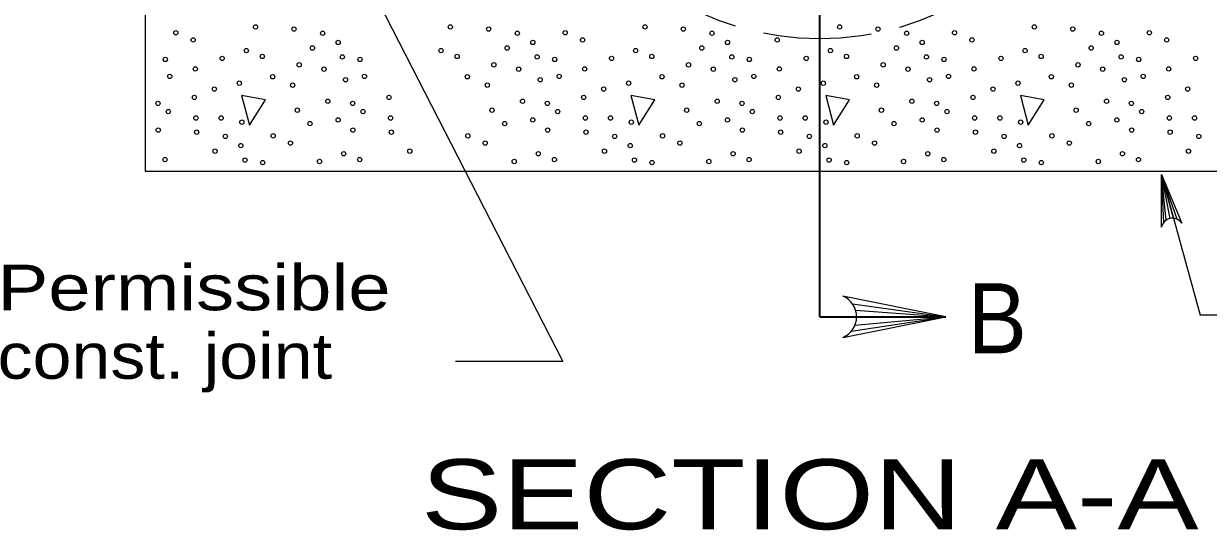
# Model space of a CAD drawing. Extents: x -410.5 to -376.5, y 1617.6 to 1661.6.
# Drawn here: x -405.776 to -401.715, y 1628.914 to 1630.65 of the extents above; entities that cross this region are included whole.
import ezdxf
from ezdxf.enums import TextEntityAlignment as Align

# ---------------------------------------------------------------- set-up
doc = ezdxf.new("R2010")
doc.units = 0
doc.header["$LTSCALE"] = 0.062
doc.linetypes.add('LONG_DASHED', pattern=[7.5, 6, -1.5])
doc.layers.add('1', color=7, linetype='Continuous', lineweight=13)

msp = doc.modelspace()

# ---------------------------------------------------------------- linework, layer by layer
at = {"layer": '1', "lineweight": 35}
for q in [(-403.04708, 1633.76367), (-402.61442, 1629.64583)]:
    msp.add_line((-403.04708, 1629.64583), q, dxfattribs=at)
at = {"layer": '1'}
for p, q in [((-401.84525, 1629.983), (-401.87542, 1630.13317)), ((-401.85883, 1629.97742), (-401.87542, 1630.13317)), ((-401.86775, 1629.96933), (-401.87542, 1630.13317)), ((-401.83383, 1629.98367), (-401.87542, 1630.13317)), ((-401.82183, 1629.9805), (-401.87542, 1630.13317)), ((-401.87542, 1630.13317), (-401.74308, 1629.65108)), ((-402.93492, 1629.69067), (-402.61442, 1629.64583)), ((-402.92408, 1629.6685), (-402.61442, 1629.64583)), ((-402.93875, 1629.59625), (-402.61442, 1629.64583)), ((-402.92642, 1629.617), (-402.61442, 1629.64583)), ((-402.92075, 1629.64583), (-402.61442, 1629.64583)), ((-401.39967, 1629.65108), (-401.74308, 1629.65108))]:
    msp.add_line(p, q, dxfattribs=at)
at = {"layer": '1', "lineweight": 25}
msp.add_lwpolyline([(-405.35992, 1632.79283), (-405.35992, 1630.1455), (-400.73433, 1630.1455), (-400.73433, 1631.78042), (-401.67833, 1631.78042), (-401.67833, 1631.72667)], dxfattribs=at)
at = {"layer": '1'}
for points in [[(-404.67042, 1630.94067), (-403.92808, 1629.49258), (-404.29583, 1629.49258)], [(-401.87525, 1629.95267), (-401.87542, 1630.13317), (-401.80583, 1629.96667)], [(-402.96842, 1629.575), (-402.61442, 1629.64583), (-402.96842, 1629.71658)]]:
    msp.add_lwpolyline(points, dxfattribs=at)
for points in [[(-405.02917, 1630.40475), (-405.00225, 1630.30242), (-404.94733, 1630.38892)], [(-403.69425, 1630.40475), (-403.66725, 1630.30242), (-403.61225, 1630.38892)], [(-403.02667, 1630.40475), (-402.99975, 1630.30242), (-402.94475, 1630.38892)], [(-402.35917, 1630.40475), (-402.33217, 1630.30242), (-402.27725, 1630.38892)]]:
    msp.add_lwpolyline(points, close=True, dxfattribs=at)
for centre, radius, start, end in [((-401.83768, 1629.94566), 0.0382, 33.46296, 169.28909), ((-402.99703, 1629.64588), 0.0764, 292.08605, 67.91218)]:
    msp.add_arc(centre, radius, start, end, dxfattribs=at)
at = {"layer": '1', "linetype": 'LONG_DASHED'}
msp.add_ellipse((-403.04711, 1631.69879), major_axis=(0, 1.09937), ratio=0.944543, start_param=2.0646245, end_param=4.2189121, dxfattribs=at)
at = {"layer": '1'}
for centre, major_axis in [((-404.98138, 1630.63915), (0, -0.00756)), ((-404.84955, 1630.63185), (0, -0.00756)), ((-404.31388, 1630.63915), (0, -0.00756)), ((-404.18204, 1630.63185), (0, -0.00756)), ((-403.64637, 1630.63915), (0, -0.00756)), ((-403.51453, 1630.63185), (0, -0.00756)), ((-402.97886, 1630.63915), (0, -0.00756)), ((-402.84703, 1630.63185), (0, -0.00756)), ((-402.31135, 1630.63915), (0, -0.00756)), ((-402.17952, 1630.63185), (0, -0.00756)), ((-405.25478, 1630.61942), (0, -0.00756)), ((-405.19532, 1630.59463), (0, -0.00756)), ((-404.75126, 1630.61754), (0, 0.00756)), ((-404.69814, 1630.58603), (0, 0.00756)), ((-404.08375, 1630.61754), (0, 0.00756)), ((-404.03063, 1630.58603), (0, 0.00756)), ((-403.91977, 1630.61942), (0, -0.00756)), ((-403.8603, 1630.59463), (0, -0.00756)), ((-403.41624, 1630.61754), (0, 0.00756)), ((-403.36312, 1630.58603), (0, 0.00756)), ((-403.1928, 1630.59463), (0, -0.00756)), ((-402.74874, 1630.61754), (0, 0.00756)), ((-402.69561, 1630.58603), (0, 0.00756)), ((-402.58475, 1630.61942), (0, -0.00756)), ((-402.52529, 1630.59463), (0, -0.00756)), ((-402.08123, 1630.61754), (0, 0.00756)), ((-402.0281, 1630.58603), (0, 0.00756)), ((-401.91724, 1630.61942), (0, -0.00756)), ((-401.85778, 1630.59463), (0, -0.00756)), ((-405.01292, 1630.55806), (0, -0.00756)), ((-404.78647, 1630.56695), (0, 0.00756)), ((-404.34542, 1630.55806), (0, -0.00756)), ((-404.11896, 1630.56695), (0, 0.00756)), ((-403.67791, 1630.55806), (0, -0.00756)), ((-403.45146, 1630.56695), (0, 0.00756)), ((-403.0104, 1630.55806), (0, -0.00756)), ((-402.78395, 1630.56695), (0, 0.00756)), ((-402.34289, 1630.55806), (0, -0.00756)), ((-402.11644, 1630.56695), (0, 0.00756)), ((-405.29083, 1630.52779), (0, -0.00756)), ((-405.09586, 1630.53138), (0, -0.00756)), ((-404.95797, 1630.53804), (0, -0.00756)), ((-404.83181, 1630.50942), (0, 0.00756)), ((-404.68368, 1630.53645), (0, 0.00756)), ((-404.62332, 1630.52779), (0, -0.00756)), ((-404.29046, 1630.53804), (0, -0.00756)), ((-404.1643, 1630.50942), (0, 0.00756)), ((-404.01617, 1630.53645), (0, 0.00756)), ((-403.95581, 1630.52779), (0, -0.00756)), ((-403.76085, 1630.53138), (0, -0.00756)), ((-403.62295, 1630.53804), (0, -0.00756)), ((-403.49679, 1630.50942), (0, 0.00756)), ((-403.34866, 1630.53645), (0, 0.00756)), ((-403.2883, 1630.52779), (0, -0.00756)), ((-403.09334, 1630.53138), (0, -0.00756)), ((-402.95544, 1630.53804), (0, -0.00756)), ((-402.82928, 1630.50942), (0, 0.00756)), ((-402.68115, 1630.53645), (0, 0.00756)), ((-402.6208, 1630.52779), (0, -0.00756)), ((-402.42583, 1630.53138), (0, -0.00756)), ((-402.28793, 1630.53804), (0, -0.00756)), ((-402.16177, 1630.50942), (0, 0.00756)), ((-402.01364, 1630.53645), (0, 0.00756)), ((-401.95329, 1630.52779), (0, -0.00756)), ((-401.75832, 1630.53138), (0, -0.00756)), ((-405.27553, 1630.46966), (0, -0.00756)), ((-405.18809, 1630.49534), (0, -0.00756)), ((-404.92287, 1630.46837), (0, 0.00756)), ((-404.74681, 1630.49446), (0, 0.00756)), ((-404.60802, 1630.46966), (0, -0.00756)), ((-404.25536, 1630.46837), (0, 0.00756)), ((-404.0793, 1630.49446), (0, 0.00756)), ((-403.94052, 1630.46966), (0, -0.00756)), ((-403.85307, 1630.49534), (0, -0.00756)), ((-403.58785, 1630.46837), (0, 0.00756)), ((-403.41179, 1630.49446), (0, 0.00756)), ((-403.27301, 1630.46966), (0, -0.00756)), ((-403.18556, 1630.49534), (0, -0.00756)), ((-402.92034, 1630.46837), (0, 0.00756)), ((-402.74429, 1630.49446), (0, 0.00756)), ((-402.6055, 1630.46966), (0, -0.00756)), ((-402.51806, 1630.49534), (0, -0.00756)), ((-402.25283, 1630.46837), (0, 0.00756)), ((-402.07678, 1630.49446), (0, 0.00756)), ((-401.93799, 1630.46966), (0, -0.00756)), ((-401.85055, 1630.49534), (0, -0.00756)), ((-405.12295, 1630.42638), (0, -0.00756)), ((-405.03729, 1630.4464), (0, -0.00756)), ((-404.85434, 1630.43975), (0, 0.00756)), ((-404.67294, 1630.45818), (0, 0.00756)), ((-404.18683, 1630.43975), (0, 0.00756)), ((-404.00543, 1630.45818), (0, 0.00756)), ((-403.78793, 1630.42638), (0, -0.00756)), ((-403.70227, 1630.4464), (0, -0.00756)), ((-403.51932, 1630.43975), (0, 0.00756)), ((-403.33792, 1630.45818), (0, 0.00756)), ((-403.12043, 1630.42638), (0, -0.00756)), ((-403.03476, 1630.4464), (0, -0.00756)), ((-402.85181, 1630.43975), (0, 0.00756)), ((-402.67041, 1630.45818), (0, 0.00756)), ((-402.45292, 1630.42638), (0, -0.00756)), ((-402.36725, 1630.4464), (0, -0.00756)), ((-402.1843, 1630.43975), (0, 0.00756)), ((-402.00291, 1630.45818), (0, 0.00756)), ((-401.78541, 1630.42638), (0, -0.00756)), ((-405.19137, 1630.39776), (0, -0.00756)), ((-404.73357, 1630.38445), (0, 0.00756)), ((-404.52386, 1630.39776), (0, -0.00756)), ((-404.06606, 1630.38445), (0, 0.00756)), ((-403.85635, 1630.39776), (0, -0.00756)), ((-403.39856, 1630.38445), (0, 0.00756)), ((-403.18885, 1630.39776), (0, -0.00756)), ((-402.73105, 1630.38445), (0, 0.00756)), ((-402.52134, 1630.39776), (0, -0.00756)), ((-402.06354, 1630.38445), (0, 0.00756)), ((-401.85383, 1630.39776), (0, -0.00756)), ((-405.31603, 1630.37709), (0, 0.00756)), ((-405.2806, 1630.34911), (0, -0.00756)), ((-404.83809, 1630.35388), (0, 0.00756)), ((-404.64852, 1630.37709), (0, 0.00756)), ((-404.61309, 1630.34911), (0, -0.00756)), ((-404.17058, 1630.35388), (0, 0.00756)), ((-403.98101, 1630.37709), (0, 0.00756)), ((-403.94558, 1630.34911), (0, -0.00756)), ((-403.50308, 1630.35388), (0, 0.00756)), ((-403.3135, 1630.37709), (0, 0.00756)), ((-403.27807, 1630.34911), (0, -0.00756)), ((-402.83557, 1630.35388), (0, 0.00756)), ((-402.64599, 1630.37709), (0, 0.00756)), ((-402.61056, 1630.34911), (0, -0.00756)), ((-402.16806, 1630.35388), (0, 0.00756)), ((-401.97849, 1630.37709), (0, 0.00756)), ((-401.94305, 1630.34911), (0, -0.00756)), ((-405.18598, 1630.32715), (0, -0.00756)), ((-405.09942, 1630.32715), (0, 0.00756)), ((-405.02828, 1630.31284), (0, -0.00756)), ((-404.79482, 1630.30806), (0, 0.00756)), ((-404.69842, 1630.32049), (0, 0.00756)), ((-404.51847, 1630.32715), (0, -0.00756)), ((-404.12731, 1630.30806), (0, 0.00756)), ((-404.03091, 1630.32049), (0, 0.00756)), ((-403.85096, 1630.32715), (0, -0.00756)), ((-403.76441, 1630.32715), (0, 0.00756)), ((-403.69326, 1630.31284), (0, -0.00756)), ((-403.4598, 1630.30806), (0, 0.00756)), ((-403.3634, 1630.32049), (0, 0.00756)), ((-403.18345, 1630.32715), (0, -0.00756)), ((-403.0969, 1630.32715), (0, 0.00756)), ((-403.02575, 1630.31284), (0, -0.00756)), ((-402.79229, 1630.30806), (0, 0.00756)), ((-402.69589, 1630.32049), (0, 0.00756)), ((-402.51594, 1630.32715), (0, -0.00756)), ((-402.42939, 1630.32715), (0, 0.00756)), ((-402.35824, 1630.31284), (0, -0.00756)), ((-402.12478, 1630.30806), (0, 0.00756)), ((-402.02838, 1630.32049), (0, 0.00756)), ((-401.84843, 1630.32715), (0, -0.00756)), ((-401.76188, 1630.32715), (0, 0.00756)), ((-405.31514, 1630.2858), (0, -0.00756)), ((-405.18331, 1630.2785), (0, -0.00756)), ((-405.08502, 1630.26419), (0, 0.00756)), ((-404.92103, 1630.26608), (0, -0.00756)), ((-404.64763, 1630.2858), (0, -0.00756)), ((-404.5158, 1630.2785), (0, -0.00756)), ((-404.25352, 1630.26608), (0, -0.00756)), ((-403.98012, 1630.2858), (0, -0.00756)), ((-403.84829, 1630.2785), (0, -0.00756)), ((-403.75, 1630.26419), (0, 0.00756)), ((-403.58601, 1630.26608), (0, -0.00756)), ((-403.31261, 1630.2858), (0, -0.00756)), ((-403.18078, 1630.2785), (0, -0.00756)), ((-403.08249, 1630.26419), (0, 0.00756)), ((-402.91851, 1630.26608), (0, -0.00756)), ((-402.6451, 1630.2858), (0, -0.00756)), ((-402.51327, 1630.2785), (0, -0.00756)), ((-402.41498, 1630.26419), (0, 0.00756)), ((-402.251, 1630.26608), (0, -0.00756)), ((-401.9776, 1630.2858), (0, -0.00756)), ((-401.84576, 1630.2785), (0, -0.00756)), ((-401.74747, 1630.26419), (0, 0.00756)), ((-405.03189, 1630.23268), (0, 0.00756)), ((-404.86157, 1630.24128), (0, -0.00756)), ((-404.19406, 1630.24128), (0, -0.00756)), ((-403.69688, 1630.23268), (0, 0.00756)), ((-403.52655, 1630.24128), (0, -0.00756)), ((-403.02937, 1630.23268), (0, 0.00756)), ((-402.85904, 1630.24128), (0, -0.00756)), ((-402.36186, 1630.23268), (0, 0.00756)), ((-402.19153, 1630.24128), (0, -0.00756)), ((-405.29172, 1630.18469), (0, -0.00756)), ((-405.12023, 1630.2136), (0, 0.00756)), ((-405.01743, 1630.1831), (0, 0.00756)), ((-404.76211, 1630.17803), (0, -0.00756)), ((-404.67917, 1630.20471), (0, -0.00756)), ((-404.62421, 1630.18469), (0, -0.00756)), ((-404.45272, 1630.2136), (0, 0.00756)), ((-404.0946, 1630.17803), (0, -0.00756)), ((-404.01166, 1630.20471), (0, -0.00756)), ((-403.9567, 1630.18469), (0, -0.00756)), ((-403.78521, 1630.2136), (0, 0.00756)), ((-403.68241, 1630.1831), (0, 0.00756)), ((-403.42709, 1630.17803), (0, -0.00756)), ((-403.34415, 1630.20471), (0, -0.00756)), ((-403.28919, 1630.18469), (0, -0.00756)), ((-403.1177, 1630.2136), (0, 0.00756)), ((-403.0149, 1630.1831), (0, 0.00756)), ((-402.75958, 1630.17803), (0, -0.00756)), ((-402.67664, 1630.20471), (0, -0.00756)), ((-402.62169, 1630.18469), (0, -0.00756)), ((-402.45019, 1630.2136), (0, 0.00756)), ((-402.3474, 1630.1831), (0, 0.00756)), ((-402.09207, 1630.17803), (0, -0.00756)), ((-402.00914, 1630.20471), (0, -0.00756)), ((-401.95418, 1630.18469), (0, -0.00756)), ((-401.78268, 1630.2136), (0, 0.00756)), ((-404.95708, 1630.17444), (0, -0.00756)), ((-403.62206, 1630.17444), (0, -0.00756)), ((-402.95455, 1630.17444), (0, -0.00756)), ((-402.28704, 1630.17444), (0, -0.00756))]:
    msp.add_ellipse(centre, major_axis=major_axis, ratio=0.944543, dxfattribs=at)

# ---------------------------------------------------------------- texts
for s, height, width, p in [('Permissible', 0.156, 1.25, (-405.866, 1629.66825)), ('const. joint', 0.156, 1.15, (-405.866, 1629.43358)), ('SECTION A-A', 0.24, 1.3, (-404.414, 1628.91767))]:
    msp.add_text(s, height=height, dxfattribs=dict(at, width=width)).set_placement(p)
at = {"layer": '1', "width": 0.95}
msp.add_text('B', height=0.24, dxfattribs=at).set_placement((-402.4385, 1629.52083), align=Align.CENTER)

doc.saveas('drawing.dxf')
